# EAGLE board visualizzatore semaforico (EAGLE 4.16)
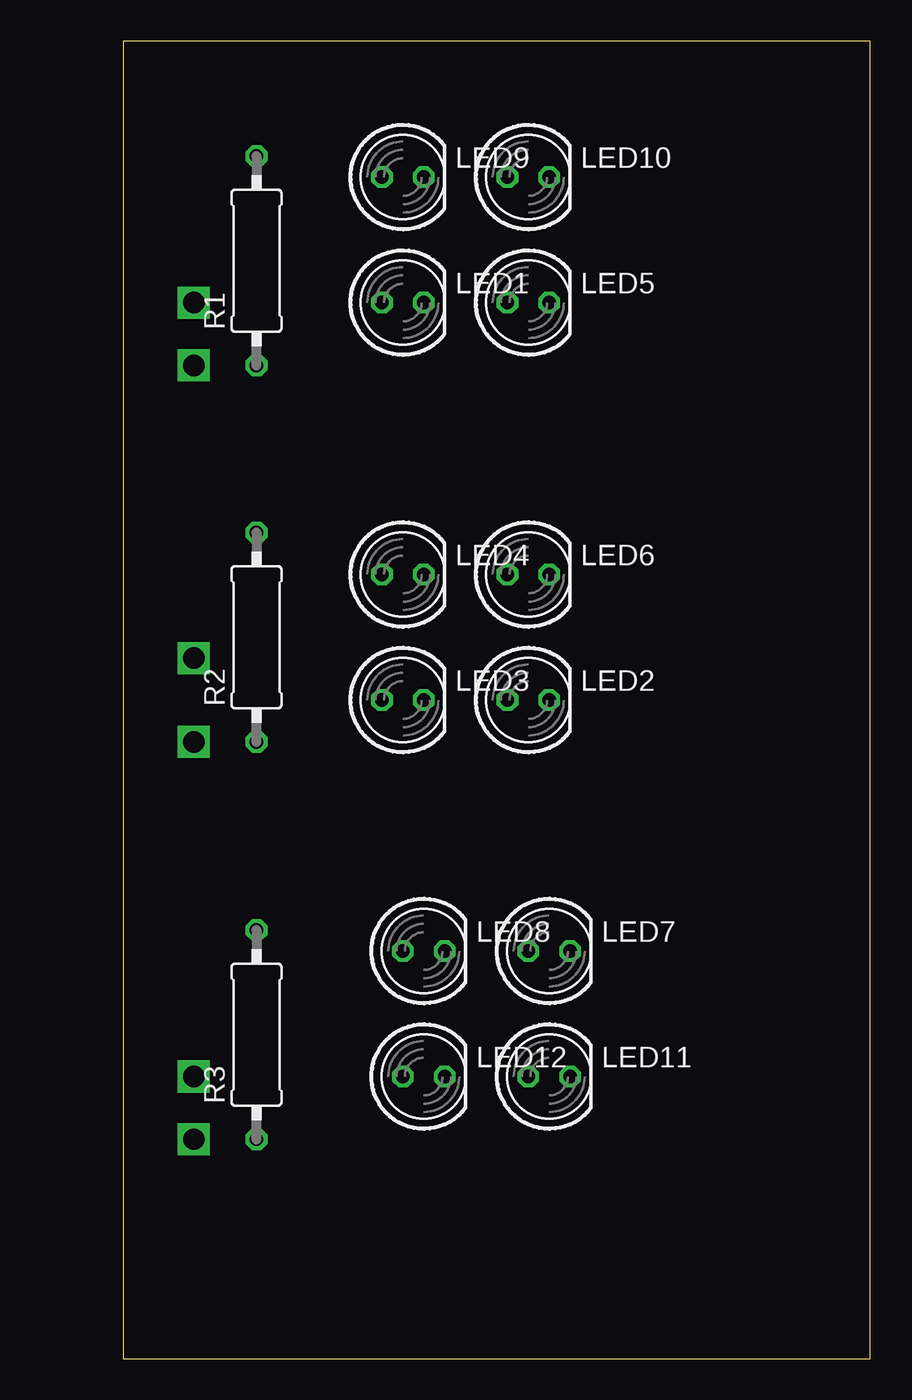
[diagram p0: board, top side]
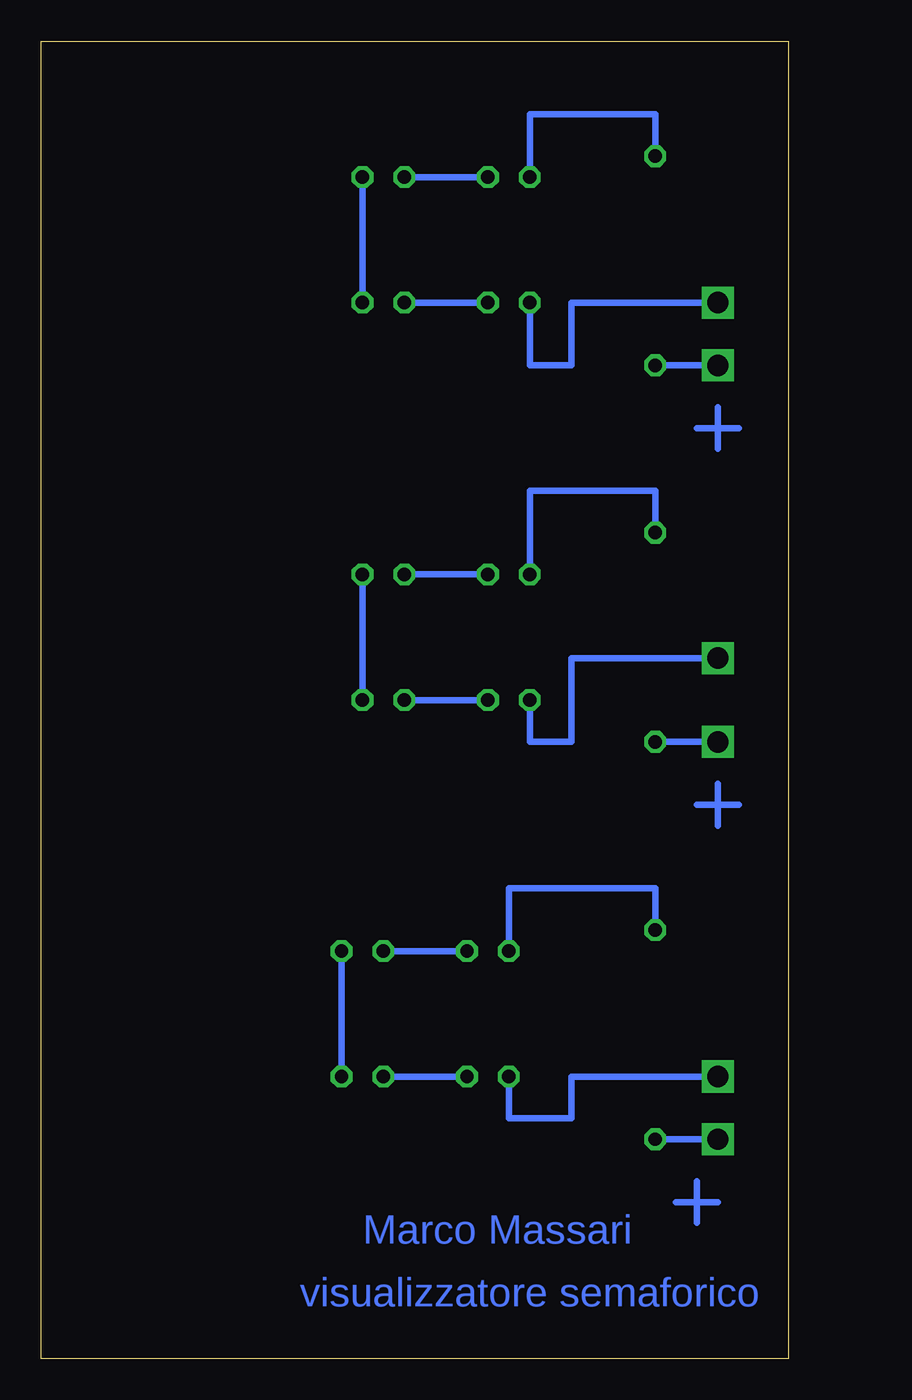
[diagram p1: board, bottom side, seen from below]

Size 45.39 x 80 mm. Coordinates in mm from the lower left corner, seen from the top.
Outline: 0,0 45.39,0 45.39,80 0,80 0,0
Copper layers (1*16): Top 0.035mm / dielectric 1.5mm / Bottom 0.035mm
Design rules "default": minimum track width 10mil, minimum drill 24mil, track to track 8mil, track to pad 8mil, pad to pad 8mil, via to via 8mil, smd to smd 8mil, copper to edge 40mil, drill to drill 8mil, minimum pad ring 10mil, minimum via ring 8mil, stop-mask expansion 4mil, vias tented up to drill 0mil, thermal gap 10mil

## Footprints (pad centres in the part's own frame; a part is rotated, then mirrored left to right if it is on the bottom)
LED5MM = drill 0.813 octagon: A -1.27,0; K 1.27,0
0309/12 = drill 0.813 octagon: 1 -6.35,0; 2 6.35,0

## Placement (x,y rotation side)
LED1  [LED5MM]  16.98,64.13 0 top
LED2  [LED5MM]  24.6,40 0 top
LED3  [LED5MM]  16.98,40 0 top
LED4  [LED5MM]  16.98,47.62 0 top
LED5  [LED5MM]  24.6,64.13 0 top
LED6  [LED5MM]  24.6,47.62 0 top
LED7  [LED5MM]  25.87,24.76 0 top
LED8  [LED5MM]  18.25,24.76 0 top
LED9  [LED5MM]  16.98,71.75 0 top
LED10  [LED5MM]  24.6,71.75 0 top
LED11  [LED5MM]  25.87,17.14 0 top
LED12  [LED5MM]  18.25,17.14 0 top
R1  [0309/12]  8.09,66.67 90 top
R2  [0309/12]  8.09,43.81 90 top
R3  [0309/12]  8.09,19.68 90 top

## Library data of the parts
LED1-LED12 = led
R1-R3 = rcl

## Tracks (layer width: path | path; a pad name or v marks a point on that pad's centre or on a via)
N$1
  Bottom 0.406: 8.09,73.02 8.09,75.56 15.71,75.56 15.71,71.75
N$2
  Bottom 0.406: 18.25,71.75 23.33,71.75
N$3
  Bottom 0.406: 25.87,71.75 25.87,64.13
N$4
  Bottom 0.406: 23.33,64.13 18.25,64.13
N$5  (via drill 1.3)
  Bottom 0.406: 15.71,64.13 15.71,60.32 13.17,60.32 13.17,64.13 v4.28,64.13
N$6  (via drill 1.3)
  Bottom 0.406: 8.09,60.32 v4.28,60.32
N$7
  Bottom 0.406: 8.09,50.16 8.09,52.7 15.71,52.7 15.71,47.62
N$8
  Bottom 0.406: 18.25,47.62 23.33,47.62
N$9
  Bottom 0.406: 25.87,47.62 25.87,40
N$10
  Bottom 0.406: 23.33,40 18.25,40
N$11  (via drill 1.3)
  Bottom 0.406: 15.71,40 15.71,37.46 13.17,37.46 13.17,42.54 v4.28,42.54
N$12  (via drill 1.3)
  Bottom 0.406: v4.28,37.46 8.09,37.46
N$13
  Bottom 0.406: 8.09,26.03 8.09,28.57 16.98,28.57 16.98,24.76
N$14
  Bottom 0.406: 19.52,24.76 24.6,24.76
N$15
  Bottom 0.406: 27.14,24.76 27.14,17.14
N$16
  Bottom 0.406: 24.6,17.14 19.52,17.14
N$17  (via drill 1.3)
  Bottom 0.406: 16.98,17.14 16.98,14.6 13.17,14.6 13.17,17.14 v4.28,17.14
N$18  (via drill 1.3)
  Bottom 0.406: v4.28,13.33 8.09,13.33
N$19
  Bottom 0.406: 4.28,57.78 4.28,55.24
N$20
  Bottom 0.406: 3.01,56.51 5.55,56.51
N$21
  Bottom 0.406: 3.01,33.65 5.55,33.65
N$22
  Bottom 0.406: 4.28,34.92 4.28,32.38
N$23
  Bottom 0.406: 5.55,10.79 5.55,8.25
N$24
  Bottom 0.406: 4.28,9.52 6.82,9.52

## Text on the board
Bottom: Marco Massari | visualizzatore semaforico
